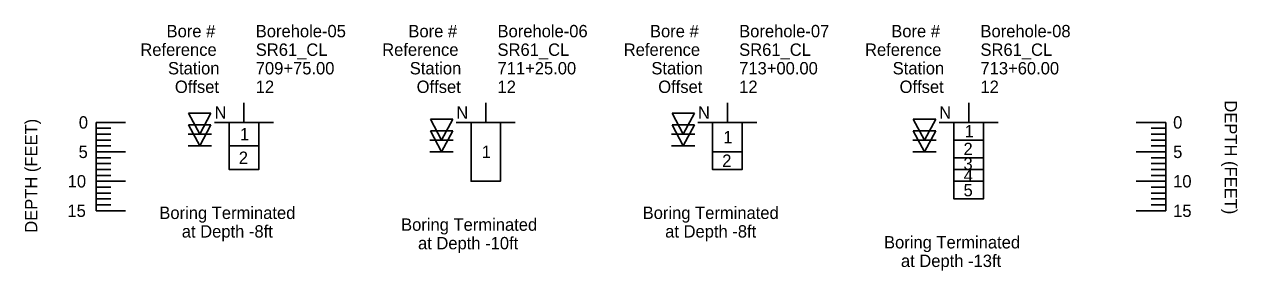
# Model space of a CAD drawing. Extents: x -27 to 179, y -25 to 17.
import ezdxf

# ---------------------------------------------------------------- set-up
doc = ezdxf.new("R2010")
doc.units = 0
for name, color, linetype in [('Default', 7, 'Continuous'), ('SoilBoxes_px', 7, 'Continuous'), ('TextGeotech', 7, 'Continuous'), ('Water_px', 7, 'Continuous')]:
    doc.layers.add(name, color=color, linetype=linetype)

# ---------------------------------------------------------------- blocks, each defined once
blk = doc.blocks.new('0hr-WaterElev')
at = {"layer": 'Water_px'}
for p, q in [((-0.00527, 0.00992), (0, 0)), ((-0.00527, 0.00992), (0.00527, 0.00992)), ((0, 0), (0.00527, 0.00992)), ((-0.0055, 0), (0.0055, 0))]:
    blk.add_line(p, q, dxfattribs=at)
blk = doc.blocks.new('24hr-WaterElev')
at = {"layer": 'Water_px'}
for p, q in [((-0.00527, 0.00992), (0, 0)), ((0.00527, 0.00992), (-0.00527, 0.00992)), ((0, 0), (0.00527, 0.00992)), ((-0.0055, 0), (0.0055, 0))]:
    blk.add_line(p, q, dxfattribs=at)

msp = doc.modelspace()

# ---------------------------------------------------------------- linework, layer by layer
at = {"layer": 'SoilBoxes_px'}
for p, q in [((10, 0), (10, 3.33)), ((51.04, 0), (51.04, 3.33)), ((92.06, 0), (92.06, 3.33)), ((133.02, 0), (133.02, 3.33)), ((-15.09, 0), (-15.09, -15)), ((-15.09, 0), (-10.09, 0)), ((-15.09, 0), (-12.59, 0)), ((5, 0), (15, 0)), ((46.04, 0), (56.04, 0)), ((87.06, 0), (97.06, 0)), ((128.02, 0), (138.02, 0)), ((166.48, 0), (161.48, 0)), ((166.48, 0), (163.98, 0)), ((166.48, 0), (166.48, -15)), ((-15.09, -1), (-12.59, -1)), ((-15.09, -2), (-12.59, -2)), ((166.48, -1), (163.98, -1)), ((166.48, -2), (163.98, -2)), ((-15.09, -3), (-12.59, -3)), ((-15.09, -4), (-12.59, -4)), ((166.48, -3), (163.98, -3)), ((166.48, -4), (163.98, -4)), ((-15.09, -5), (-10.09, -5)), ((-15.09, -5), (-12.59, -5)), ((-15.09, -6), (-12.59, -6)), ((166.48, -5), (161.48, -5)), ((166.48, -5), (163.98, -5)), ((166.48, -6), (163.98, -6)), ((-15.09, -7), (-12.59, -7)), ((-15.09, -8), (-12.59, -8)), ((166.48, -7), (163.98, -7)), ((166.48, -8), (163.98, -8)), ((-15.09, -9), (-12.59, -9)), ((-15.09, -10), (-10.09, -10)), ((-15.09, -10), (-12.59, -10)), ((166.48, -10), (161.48, -10)), ((166.48, -9), (163.98, -9)), ((166.48, -10), (163.98, -10)), ((-15.09, -11), (-12.59, -11)), ((-15.09, -12), (-12.59, -12)), ((166.48, -11), (163.98, -11)), ((166.48, -12), (163.98, -12)), ((-15.09, -13), (-12.59, -13)), ((-15.09, -14), (-12.59, -14)), ((166.48, -13), (163.98, -13)), ((166.48, -14), (163.98, -14)), ((-15.09, -15), (-10.09, -15)), ((-15.09, -15), (-12.59, -15)), ((166.48, -15), (161.48, -15)), ((166.48, -15), (163.98, -15))]:
    msp.add_line(p, q, dxfattribs=at)
for points in [[(7.5, 0), (12.5, 0), (12.5, -4), (7.5, -4)], [(48.54, 0), (53.54, 0), (53.54, -10), (48.54, -10)], [(89.56, 0), (94.56, 0), (94.56, -5), (89.56, -5)], [(130.52, 0), (135.52, 0), (135.52, -3), (130.52, -3)], [(7.5, -4), (12.5, -4), (12.5, -8), (7.5, -8)], [(130.52, -3), (135.52, -3), (135.52, -6), (130.52, -6)], [(89.56, -5), (94.56, -5), (94.56, -8), (89.56, -8)], [(130.52, -6), (135.52, -6), (135.52, -8), (130.52, -8)], [(130.52, -8), (135.52, -8), (135.52, -10), (130.52, -10)], [(130.52, -10), (135.52, -10), (135.52, -13), (130.52, -13)]]:
    msp.add_lwpolyline(points, close=True, dxfattribs=at)

# ---------------------------------------------------------------- block references
at = {"layer": 'Default', "xscale": 360, "yscale": 360}
for name, p in [('0hr-WaterElev', (2.5, -2)), ('0hr-WaterElev', (43.54, -3)), ('0hr-WaterElev', (84.56, -2)), ('0hr-WaterElev', (125.52, -3)), ('24hr-WaterElev', (2.5, -4)), ('24hr-WaterElev', (43.54, -5)), ('24hr-WaterElev', (84.56, -4)), ('24hr-WaterElev', (125.52, -5))]:
    msp.add_blockref(name, p, dxfattribs=at)

# ---------------------------------------------------------------- texts
at = {"layer": 'TextGeotech'}
for s, p in [('Bore #', (-3.14, 14.45)), ('Borehole-05', (12, 14.45)), ('Bore #', (37.91, 14.45)), ('Borehole-06', (53.04, 14.45)), ('Bore #', (78.92, 14.45)), ('Borehole-07', (94.06, 14.45)), ('Bore #', (119.88, 14.45)), ('Borehole-08', (135.02, 14.45)), ('Reference', (-7.59, 11.3)), ('SR61_CL', (12, 11.3)), ('Reference', (33.46, 11.3)), ('SR61_CL', (53.04, 11.3)), ('Reference', (74.47, 11.3)), ('SR61_CL', (94.06, 11.3)), ('Reference', (115.43, 11.3)), ('SR61_CL', (135.02, 11.3)), ('Station', (-2.9, 8.15)), ('Station', (38.14, 8.15)), ('Station', (79.16, 8.15)), ('Station', (120.12, 8.15)), ('709+75.00', (12, 8.15)), ('711+25.00', (53.04, 8.15)), ('713+00.00', (94.06, 8.15)), ('713+60.00', (135.02, 8.15)), ('Offset', (-1.73, 5)), ('12', (12, 5)), ('Offset', (39.31, 5)), ('12', (53.04, 5)), ('Offset', (80.32, 5)), ('12', (94.06, 5)), ('Offset', (121.29, 5)), ('12', (135.02, 5)), ('N', (5, 0.62)), ('N', (46.04, 0.62)), ('N', (87.06, 0.62)), ('N', (128.02, 0.62)), ('0', (-18.04, -1.05)), ('0', (167.73, -1.05)), ('1', (9.31, -3.05)), ('1', (91.37, -3.55)), ('1', (132.33, -2.55)), ('5', (-18.08, -6.05)), ('1', (50.35, -6.05)), ('2', (132.14, -5.55)), ('5', (167.73, -6.05)), ('2', (9.12, -7.05)), ('2', (91.18, -7.55)), ('3', (132.14, -8.05)), ('4', (132.18, -10.05)), ('10', (-19.93, -11.05)), ('10', (167.73, -11.05)), ('5', (132.15, -12.55)), ('15', (-19.97, -16.05)), ('Boring Terminated ', (-4.37, -16.4)), ('Boring Terminated ', (77.68, -16.4)), ('15', (167.73, -16.05)), ('Boring Terminated ', (36.67, -18.4)), (' at Depth -8ft', (-1.34, -19.55)), (' at Depth -8ft', (80.72, -19.55)), (' at Depth -10ft', (38.76, -21.55)), ('Boring Terminated ', (118.65, -21.4)), (' at Depth -13ft', (120.74, -24.55))]:
    msp.add_text(s, height=2.1, dxfattribs=at).set_placement(p)
for rotation, p in [(270, (176.48, 3.74)), (90, (-25.09, -18.74))]:
    msp.add_text('DEPTH (FEET)', height=2.1, rotation=rotation, dxfattribs=at).set_placement(p)

doc.saveas('drawing.dxf')
